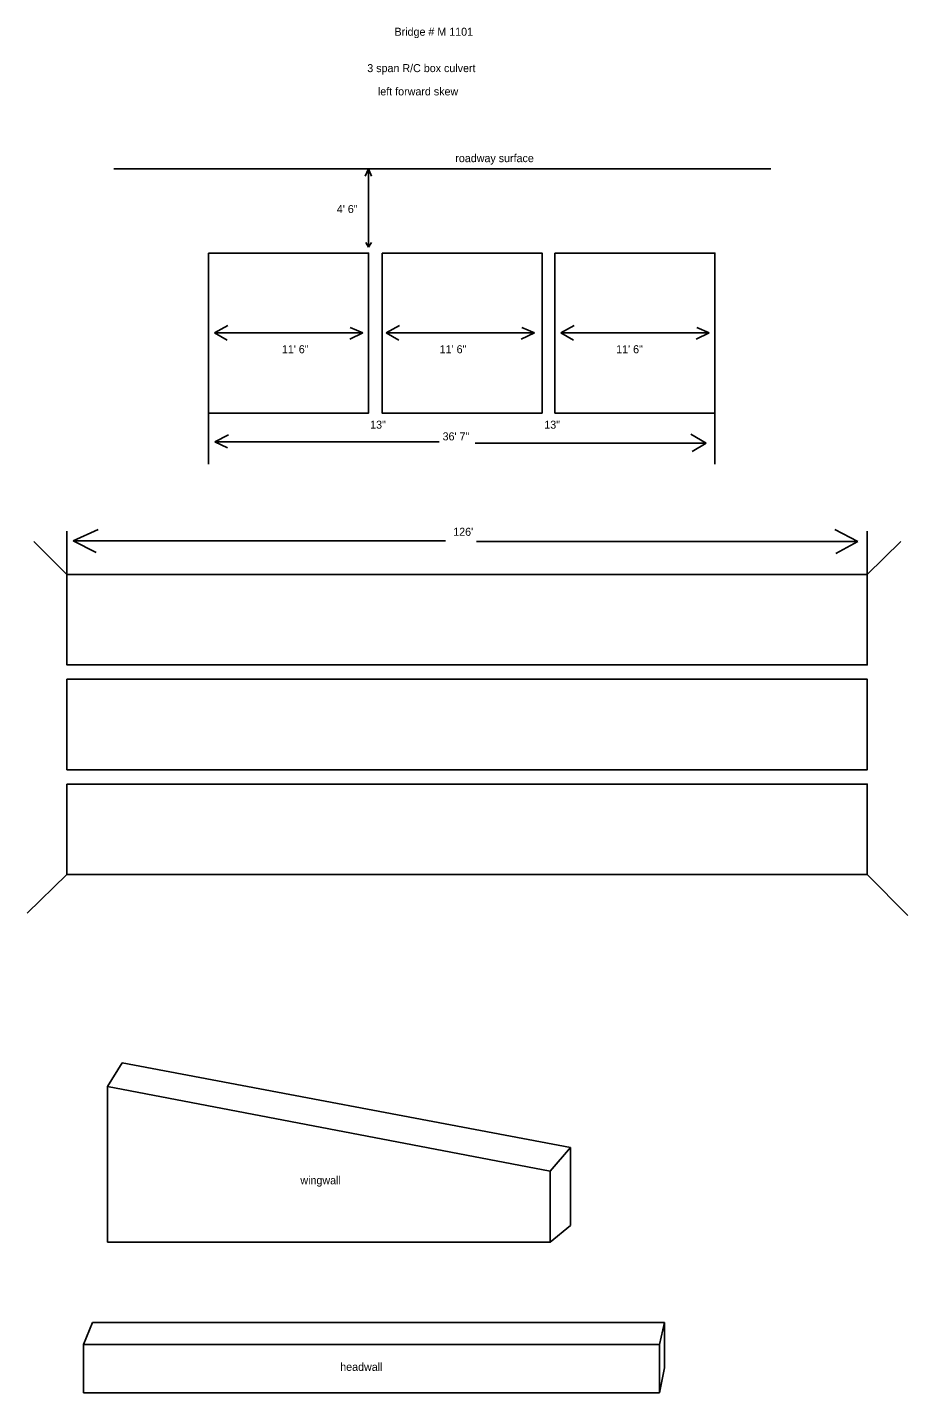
# Model space of a CAD drawing. Extents: x -629.7 to -574.7, y -353.6 to -268.3.
import ezdxf

# ---------------------------------------------------------------- set-up
doc = ezdxf.new("R2010")
doc.units = 0
doc.layers.add('Default', color=7, linetype='Continuous')

msp = doc.modelspace()

# ---------------------------------------------------------------- linework, layer by layer
at = {"layer": 'Default'}
for p, q in [((-608.404, -277.151), (-624.314, -277.151)), ((-608.404, -277.151), (-608.621, -277.594)), ((-608.404, -277.151), (-608.404, -281.469)), ((-608.404, -277.151), (-608.215, -277.605)), ((-608.404, -277.151), (-593.023, -277.151)), ((-593.023, -277.151), (-583.278, -277.151)), ((-608.404, -282.033), (-608.568, -281.752)), ((-608.404, -281.469), (-608.404, -282.033)), ((-608.404, -282.033), (-608.23, -281.752)), ((-618.035, -287.395), (-617.196, -286.924)), ((-608.765, -287.395), (-609.543, -287.047)), ((-607.312, -287.395), (-606.473, -286.924)), ((-598.042, -287.395), (-598.82, -287.047)), ((-596.39, -287.395), (-595.551, -286.924)), ((-587.12, -287.395), (-587.898, -287.047)), ((-618.035, -287.395), (-608.765, -287.395)), ((-618.035, -287.395), (-617.237, -287.845)), ((-608.765, -287.395), (-609.584, -287.784)), ((-607.312, -287.395), (-598.042, -287.395)), ((-607.312, -287.395), (-606.514, -287.845)), ((-598.042, -287.395), (-598.861, -287.784)), ((-596.39, -287.395), (-587.12, -287.395)), ((-596.39, -287.395), (-595.592, -287.845)), ((-587.12, -287.395), (-587.938, -287.784)), ((-618.404, -292.401), (-618.404, -295.589)), ((-586.759, -292.401), (-586.759, -295.589)), ((-618.014, -294.203), (-617.165, -293.767)), ((-618.014, -294.203), (-603.988, -294.203)), ((-618.014, -294.203), (-617.227, -294.576)), ((-587.319, -294.287), (-588.262, -293.706)), ((-601.749, -294.287), (-587.319, -294.287)), ((-587.319, -294.287), (-588.189, -294.794)), ((-627.248, -302.481), (-627.248, -299.775)), ((-626.864, -300.384), (-625.289, -299.667)), ((-577.839, -300.42), (-579.271, -299.667)), ((-577.248, -302.481), (-577.248, -299.775)), ((-627.248, -302.481), (-629.318, -300.418)), ((-603.587, -300.384), (-626.864, -300.384)), ((-626.864, -300.384), (-625.432, -301.1)), ((-601.653, -300.42), (-577.839, -300.42)), ((-577.839, -300.42), (-579.199, -301.172)), ((-577.248, -302.481), (-575.141, -300.418)), ((-627.248, -321.221), (-629.727, -323.642)), ((-577.248, -321.221), (-574.717, -323.769)), ((-624.713, -334.467), (-623.805, -332.984)), ((-623.805, -332.984), (-595.776, -338.273)), ((-624.713, -334.467), (-624.713, -344.186)), ((-624.713, -334.467), (-597.056, -339.743)), ((-597.056, -339.743), (-595.776, -338.273)), ((-595.776, -338.273), (-595.776, -343.139)), ((-597.056, -344.186), (-597.056, -339.743)), ((-597.056, -344.186), (-595.776, -343.139)), ((-624.713, -344.186), (-597.056, -344.186)), ((-626.212, -350.582), (-625.644, -349.207)), ((-625.644, -349.207), (-589.913, -349.207)), ((-590.23, -350.582), (-589.913, -349.207)), ((-589.913, -349.207), (-589.913, -349.207)), ((-589.913, -349.207), (-589.913, -352.038)), ((-626.212, -350.582), (-590.23, -350.582)), ((-626.212, -350.582), (-626.212, -353.582)), ((-590.23, -350.582), (-590.23, -353.582)), ((-589.913, -352.038), (-590.23, -353.582)), ((-626.212, -353.582), (-590.23, -353.582))]:
    msp.add_line(p, q, dxfattribs=at)
for points in [[(-618.404, -282.401), (-608.404, -282.401), (-608.404, -292.401), (-618.404, -292.401)], [(-607.564, -282.401), (-597.564, -282.401), (-597.564, -292.401), (-607.564, -292.401)], [(-596.759, -282.401), (-586.759, -282.401), (-586.759, -292.401), (-596.759, -292.401)], [(-627.248, -302.481), (-577.248, -302.481), (-577.248, -308.127), (-627.248, -308.127)], [(-627.248, -309.026), (-577.248, -309.026), (-577.248, -314.672), (-627.248, -314.672)], [(-627.248, -315.575), (-577.248, -315.575), (-577.248, -321.221), (-627.248, -321.221)]]:
    msp.add_lwpolyline(points, close=True, dxfattribs=at)

# ---------------------------------------------------------------- texts
for s, p in [('Bridge # M 1101', (-606.782, -268.831)), ('3 span R/C box culvert', (-608.484, -271.104)), ('left forward skew', (-607.818, -272.558)), ('roadway surface', (-602.983, -276.727)), ('4\' 6"', (-610.385, -279.903)), ('11\' 6"', (-613.82, -288.662)), ('11\' 6"', (-603.96, -288.662)), ('11\' 6"', (-592.932, -288.662)), ('13"', (-608.305, -293.373)), ('13"', (-597.423, -293.373)), ('36\' 7"', (-603.778, -294.104)), ("126'", (-603.113, -300.062)), ('wingwall', (-612.663, -340.563)), ('headwall', (-610.175, -352.218))]:
    msp.add_text(s, height=0.5, dxfattribs=at).set_placement(p)

doc.saveas('drawing.dxf')
